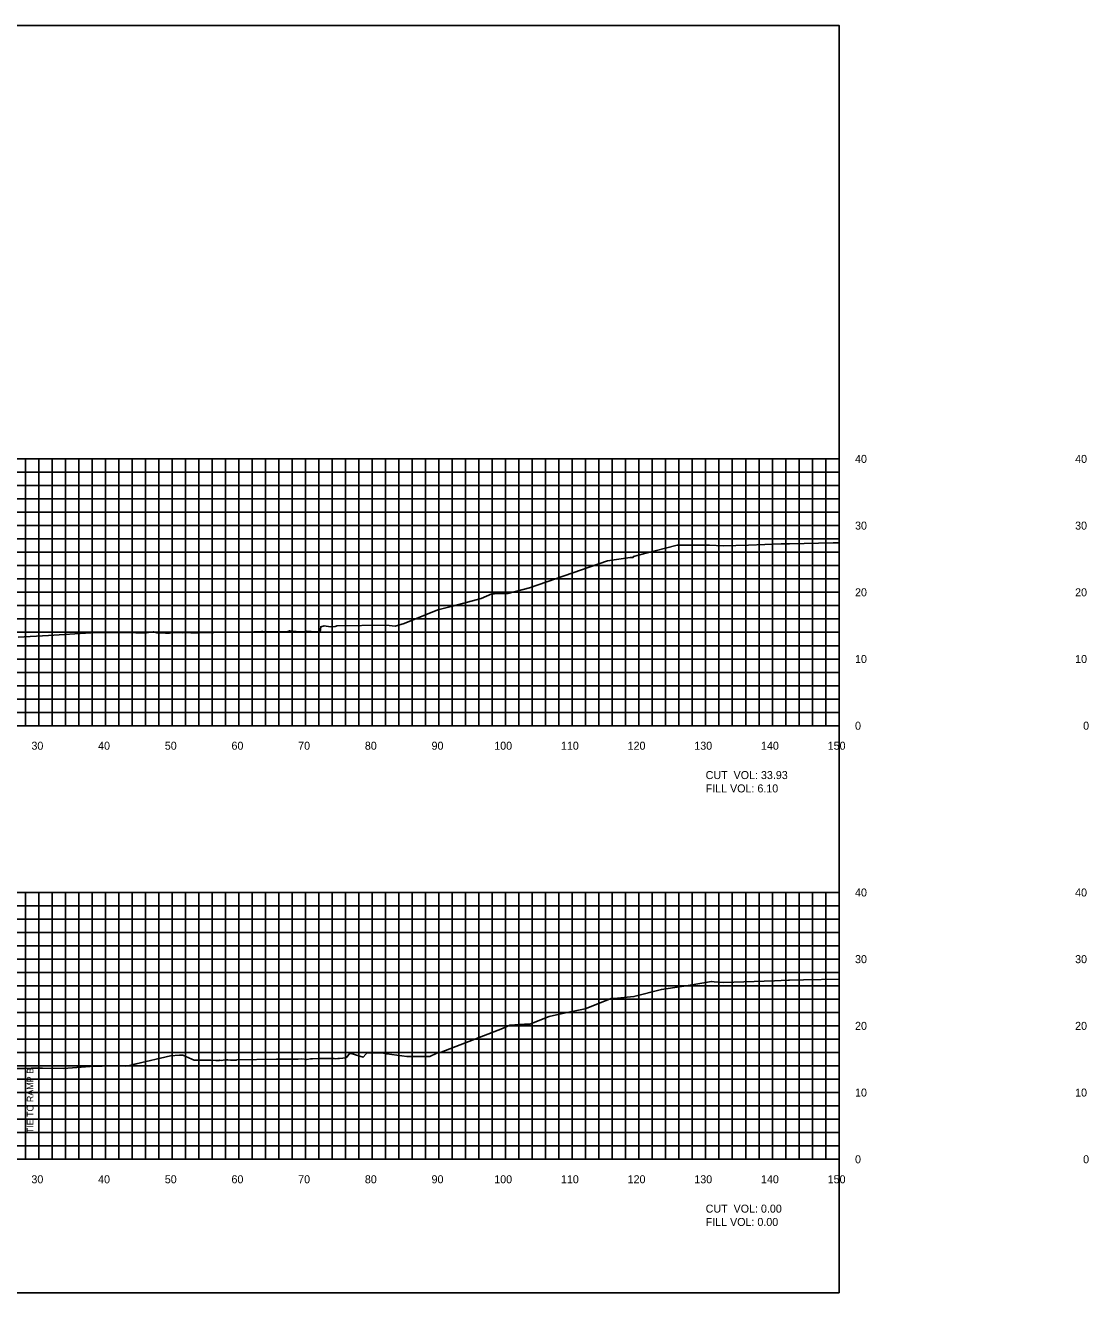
# Model space of a CAD drawing. Extents: x 1797645 to 1803805, y 248417 to 250269.
# Drawn here: x 1802319 to 1802478.4, y 250079.4 to 250269.4 of the extents above; entities that cross this region are included whole.
import ezdxf

# ---------------------------------------------------------------- set-up
doc = ezdxf.new("R2010")
doc.units = 0
for name, color, linetype in [('10', 7, 'Continuous'), ('3', 7, 'Continuous'), ('31', 7, 'Continuous'), ('60', 7, 'Continuous'), ('ANNO-TXT', 7, 'Continuous'), ('Level 62', 7, 'Continuous'), ('M-ROADS', 7, 'Continuous')]:
    doc.layers.add(name, color=color, linetype=linetype)

msp = doc.modelspace()

# ---------------------------------------------------------------- linework, layer by layer
msp.add_lwpolyline([(1802141, 250079.43), (1802441, 250079.43), (1802441, 250269.43), (1802141, 250269.43)], close=True)
at = {"layer": '60'}
for p, q in [((1802441, 250164.43), (1802441, 250204.43)), ((1802441.06, 250204.43), (1802441, 250204.43)), ((1802441.06, 250194.43), (1802441, 250194.43)), ((1802441.06, 250184.43), (1802441, 250184.43)), ((1802441.06, 250174.43), (1802441, 250174.43)), ((1802141, 250164.43), (1802441, 250164.43)), ((1802321, 250164.37), (1802321, 250164.43)), ((1802331, 250164.37), (1802331, 250164.43)), ((1802341, 250164.37), (1802341, 250164.43)), ((1802351, 250164.37), (1802351, 250164.43)), ((1802361, 250164.37), (1802361, 250164.43)), ((1802371, 250164.37), (1802371, 250164.43)), ((1802381, 250164.37), (1802381, 250164.43)), ((1802391, 250164.37), (1802391, 250164.43)), ((1802401, 250164.37), (1802401, 250164.43)), ((1802411, 250164.37), (1802411, 250164.43)), ((1802421, 250164.37), (1802421, 250164.43)), ((1802431, 250164.37), (1802431, 250164.43)), ((1802441, 250164.37), (1802441, 250164.43)), ((1802441.06, 250164.43), (1802441, 250164.43)), ((1802441, 250099.43), (1802441, 250139.43)), ((1802441.06, 250139.43), (1802441, 250139.43)), ((1802441.06, 250129.43), (1802441, 250129.43)), ((1802441.06, 250119.43), (1802441, 250119.43)), ((1802441.06, 250109.43), (1802441, 250109.43)), ((1802141, 250099.43), (1802441, 250099.43)), ((1802321, 250099.37), (1802321, 250099.43)), ((1802331, 250099.37), (1802331, 250099.43)), ((1802341, 250099.37), (1802341, 250099.43)), ((1802351, 250099.37), (1802351, 250099.43)), ((1802361, 250099.37), (1802361, 250099.43)), ((1802371, 250099.37), (1802371, 250099.43)), ((1802381, 250099.37), (1802381, 250099.43)), ((1802391, 250099.37), (1802391, 250099.43)), ((1802401, 250099.37), (1802401, 250099.43)), ((1802411, 250099.37), (1802411, 250099.43)), ((1802421, 250099.37), (1802421, 250099.43)), ((1802431, 250099.37), (1802431, 250099.43)), ((1802441, 250099.37), (1802441, 250099.43)), ((1802441.06, 250099.43), (1802441, 250099.43))]:
    msp.add_line(p, q, dxfattribs=at)
at = {"layer": 'Level 62'}
for p, q in [((1802141, 250204.43), (1802441, 250204.43)), ((1802319, 250164.43), (1802319, 250204.43)), ((1802321, 250164.43), (1802321, 250204.43)), ((1802323, 250164.43), (1802323, 250204.43)), ((1802325, 250164.43), (1802325, 250204.43)), ((1802327, 250164.43), (1802327, 250204.43)), ((1802329, 250164.43), (1802329, 250204.43)), ((1802331, 250164.43), (1802331, 250204.43)), ((1802333, 250164.43), (1802333, 250204.43)), ((1802335, 250164.43), (1802335, 250204.43)), ((1802337, 250164.43), (1802337, 250204.43)), ((1802339, 250164.43), (1802339, 250204.43)), ((1802341, 250164.43), (1802341, 250204.43)), ((1802343, 250164.43), (1802343, 250204.43)), ((1802345, 250164.43), (1802345, 250204.43)), ((1802347, 250164.43), (1802347, 250204.43)), ((1802349, 250164.43), (1802349, 250204.43)), ((1802351, 250164.43), (1802351, 250204.43)), ((1802353, 250164.43), (1802353, 250204.43)), ((1802355, 250164.43), (1802355, 250204.43)), ((1802357, 250164.43), (1802357, 250204.43)), ((1802359, 250164.43), (1802359, 250204.43)), ((1802361, 250164.43), (1802361, 250204.43)), ((1802363, 250164.43), (1802363, 250204.43)), ((1802365, 250164.43), (1802365, 250204.43)), ((1802367, 250164.43), (1802367, 250204.43)), ((1802369, 250164.43), (1802369, 250204.43)), ((1802371, 250164.43), (1802371, 250204.43)), ((1802373, 250164.43), (1802373, 250204.43)), ((1802375, 250164.43), (1802375, 250204.43)), ((1802377, 250164.43), (1802377, 250204.43)), ((1802379, 250164.43), (1802379, 250204.43)), ((1802381, 250164.43), (1802381, 250204.43)), ((1802383, 250164.43), (1802383, 250204.43)), ((1802385, 250164.43), (1802385, 250204.43)), ((1802387, 250164.43), (1802387, 250204.43)), ((1802389, 250164.43), (1802389, 250204.43)), ((1802391, 250164.43), (1802391, 250204.43)), ((1802393, 250164.43), (1802393, 250204.43)), ((1802395, 250164.43), (1802395, 250204.43)), ((1802397, 250164.43), (1802397, 250204.43)), ((1802399, 250164.43), (1802399, 250204.43)), ((1802401, 250164.43), (1802401, 250204.43)), ((1802403, 250164.43), (1802403, 250204.43)), ((1802405, 250164.43), (1802405, 250204.43)), ((1802407, 250164.43), (1802407, 250204.43)), ((1802409, 250164.43), (1802409, 250204.43)), ((1802411, 250164.43), (1802411, 250204.43)), ((1802413, 250164.43), (1802413, 250204.43)), ((1802415, 250164.43), (1802415, 250204.43)), ((1802417, 250164.43), (1802417, 250204.43)), ((1802419, 250164.43), (1802419, 250204.43)), ((1802421, 250164.43), (1802421, 250204.43)), ((1802423, 250164.43), (1802423, 250204.43)), ((1802425, 250164.43), (1802425, 250204.43)), ((1802427, 250164.43), (1802427, 250204.43)), ((1802429, 250164.43), (1802429, 250204.43)), ((1802431, 250164.43), (1802431, 250204.43)), ((1802433, 250164.43), (1802433, 250204.43)), ((1802435, 250164.43), (1802435, 250204.43)), ((1802437, 250164.43), (1802437, 250204.43)), ((1802439, 250164.43), (1802439, 250204.43)), ((1802441, 250164.43), (1802441, 250204.43)), ((1802141, 250202.43), (1802441, 250202.43)), ((1802141, 250200.43), (1802441, 250200.43)), ((1802141, 250198.43), (1802441, 250198.43)), ((1802141, 250196.43), (1802441, 250196.43)), ((1802141, 250194.43), (1802441, 250194.43)), ((1802141, 250192.43), (1802441, 250192.43)), ((1802141, 250190.43), (1802441, 250190.43)), ((1802141, 250188.43), (1802441, 250188.43)), ((1802141, 250186.43), (1802441, 250186.43)), ((1802141, 250184.43), (1802441, 250184.43)), ((1802141, 250182.43), (1802441, 250182.43)), ((1802141, 250180.43), (1802441, 250180.43)), ((1802141, 250178.43), (1802441, 250178.43)), ((1802141, 250176.43), (1802441, 250176.43)), ((1802141, 250174.43), (1802441, 250174.43)), ((1802141, 250172.43), (1802441, 250172.43)), ((1802141, 250170.43), (1802441, 250170.43)), ((1802141, 250168.43), (1802441, 250168.43)), ((1802141, 250166.43), (1802441, 250166.43)), ((1802141, 250164.43), (1802441, 250164.43)), ((1802141, 250139.43), (1802441, 250139.43)), ((1802319, 250099.43), (1802319, 250139.43)), ((1802321, 250099.43), (1802321, 250139.43)), ((1802323, 250099.43), (1802323, 250139.43)), ((1802325, 250099.43), (1802325, 250139.43)), ((1802327, 250099.43), (1802327, 250139.43)), ((1802329, 250099.43), (1802329, 250139.43)), ((1802331, 250099.43), (1802331, 250139.43)), ((1802333, 250099.43), (1802333, 250139.43)), ((1802335, 250099.43), (1802335, 250139.43)), ((1802337, 250099.43), (1802337, 250139.43)), ((1802339, 250099.43), (1802339, 250139.43)), ((1802341, 250099.43), (1802341, 250139.43)), ((1802343, 250099.43), (1802343, 250139.43)), ((1802345, 250099.43), (1802345, 250139.43)), ((1802347, 250099.43), (1802347, 250139.43)), ((1802349, 250099.43), (1802349, 250139.43)), ((1802351, 250099.43), (1802351, 250139.43)), ((1802353, 250099.43), (1802353, 250139.43)), ((1802355, 250099.43), (1802355, 250139.43)), ((1802357, 250099.43), (1802357, 250139.43)), ((1802359, 250099.43), (1802359, 250139.43)), ((1802361, 250099.43), (1802361, 250139.43)), ((1802363, 250099.43), (1802363, 250139.43)), ((1802365, 250099.43), (1802365, 250139.43)), ((1802367, 250099.43), (1802367, 250139.43)), ((1802369, 250099.43), (1802369, 250139.43)), ((1802371, 250099.43), (1802371, 250139.43)), ((1802373, 250099.43), (1802373, 250139.43)), ((1802375, 250099.43), (1802375, 250139.43)), ((1802377, 250099.43), (1802377, 250139.43)), ((1802379, 250099.43), (1802379, 250139.43)), ((1802381, 250099.43), (1802381, 250139.43)), ((1802383, 250099.43), (1802383, 250139.43)), ((1802385, 250099.43), (1802385, 250139.43)), ((1802387, 250099.43), (1802387, 250139.43)), ((1802389, 250099.43), (1802389, 250139.43)), ((1802391, 250099.43), (1802391, 250139.43)), ((1802393, 250099.43), (1802393, 250139.43)), ((1802395, 250099.43), (1802395, 250139.43)), ((1802397, 250099.43), (1802397, 250139.43)), ((1802399, 250099.43), (1802399, 250139.43)), ((1802401, 250099.43), (1802401, 250139.43)), ((1802403, 250099.43), (1802403, 250139.43)), ((1802405, 250099.43), (1802405, 250139.43)), ((1802407, 250099.43), (1802407, 250139.43)), ((1802409, 250099.43), (1802409, 250139.43)), ((1802411, 250099.43), (1802411, 250139.43)), ((1802413, 250099.43), (1802413, 250139.43)), ((1802415, 250099.43), (1802415, 250139.43)), ((1802417, 250099.43), (1802417, 250139.43)), ((1802419, 250099.43), (1802419, 250139.43)), ((1802421, 250099.43), (1802421, 250139.43)), ((1802423, 250099.43), (1802423, 250139.43)), ((1802425, 250099.43), (1802425, 250139.43)), ((1802427, 250099.43), (1802427, 250139.43)), ((1802429, 250099.43), (1802429, 250139.43)), ((1802431, 250099.43), (1802431, 250139.43)), ((1802433, 250099.43), (1802433, 250139.43)), ((1802435, 250099.43), (1802435, 250139.43)), ((1802437, 250099.43), (1802437, 250139.43)), ((1802439, 250099.43), (1802439, 250139.43)), ((1802441, 250099.43), (1802441, 250139.43)), ((1802141, 250137.43), (1802441, 250137.43)), ((1802141, 250135.43), (1802441, 250135.43)), ((1802141, 250133.43), (1802441, 250133.43)), ((1802141, 250131.43), (1802441, 250131.43)), ((1802141, 250129.43), (1802441, 250129.43)), ((1802141, 250127.43), (1802441, 250127.43)), ((1802141, 250125.43), (1802441, 250125.43)), ((1802141, 250123.43), (1802441, 250123.43)), ((1802141, 250121.43), (1802441, 250121.43)), ((1802141, 250119.43), (1802441, 250119.43)), ((1802141, 250117.43), (1802441, 250117.43)), ((1802141, 250115.43), (1802441, 250115.43)), ((1802141, 250113.43), (1802441, 250113.43)), ((1802141, 250111.43), (1802441, 250111.43)), ((1802141, 250109.43), (1802441, 250109.43)), ((1802141, 250107.43), (1802441, 250107.43)), ((1802141, 250105.43), (1802441, 250105.43)), ((1802141, 250103.43), (1802441, 250103.43)), ((1802141, 250101.43), (1802441, 250101.43)), ((1802141, 250099.43), (1802441, 250099.43))]:
    msp.add_line(p, q, dxfattribs=at)
at = {"layer": 'M-ROADS'}
for points in [[(1802317.93, 250177.7), (1802322.45, 250177.96), (1802328.83, 250178.33), (1802333.88, 250178.42), (1802334.22, 250178.4), (1802334.74, 250178.42), (1802335.57, 250178.36), (1802337.13, 250178.33), (1802338.19, 250178.51), (1802338.73, 250178.33), (1802339.26, 250178.34), (1802340, 250178.32), (1802340.59, 250178.29), (1802341.01, 250178.39), (1802341.32, 250178.4), (1802341.87, 250178.38), (1802342.57, 250178.36), (1802343.54, 250178.38), (1802343.8, 250178.37), (1802343.88, 250178.37), (1802344.54, 250178.35), (1802345.02, 250178.35), (1802345.07, 250178.34), (1802349.46, 250178.45), (1802353.26, 250178.51), (1802354.38, 250178.53), (1802354.53, 250178.53), (1802354.69, 250178.52), (1802354.9, 250178.54), (1802355.81, 250178.52), (1802356.14, 250178.52), (1802357.04, 250178.52), (1802357.78, 250178.5), (1802358.25, 250178.49), (1802358.62, 250178.64), (1802358.65, 250178.64), (1802359.61, 250178.54), (1802360.08, 250178.49), (1802360.91, 250178.56), (1802361.13, 250178.61), (1802362.55, 250178.5), (1802362.84, 250178.48), (1802363.2, 250178.48), (1802363.29, 250179.26), (1802363.81, 250179.4), (1802364.76, 250179.24), (1802365.45, 250179.3), (1802365.61, 250179.36), (1802365.72, 250179.41), (1802365.77, 250179.41), (1802373.11, 250179.51), (1802374.46, 250179.37), (1802375.79, 250179.73), (1802380.86, 250181.8), (1802383.26, 250182.42), (1802387.32, 250183.48), (1802388.92, 250184.22), (1802389.34, 250184.22), (1802391.35, 250184.26), (1802394.61, 250185.11), (1802406.3, 250189.17), (1802409.66, 250189.66), (1802409.86, 250189.66), (1802410.11, 250189.66), (1802410.2, 250189.8), (1802411.67, 250190.18), (1802416.74, 250191.5), (1802418.78, 250191.5), (1802420.15, 250191.5), (1802421.16, 250191.5), (1802421.39, 250191.49), (1802421.57, 250191.49), (1802423.64, 250191.39), (1802427.4, 250191.52), (1802432.33, 250191.69), (1802433.03, 250191.71), (1802433.57, 250191.72), (1802440.11, 250191.85), (1802441, 250191.87)], [(1802317.22, 250113.02), (1802319, 250113.05), (1802319.88, 250113.08), (1802320.66, 250113.07), (1802321.58, 250113.07), (1802324.72, 250113.05), (1802329.38, 250113.4), (1802329.59, 250113.41), (1802330.51, 250113.41), (1802331.93, 250113.42), (1802333.68, 250113.43), (1802334, 250113.41), (1802334.45, 250113.42), (1802335.63, 250113.74), (1802340.76, 250114.94), (1802342.08, 250115.05), (1802342.62, 250115.05), (1802343.95, 250114.46), (1802344.3, 250114.3), (1802345.29, 250114.29), (1802345.55, 250114.31), (1802345.71, 250114.29), (1802346.82, 250114.28), (1802347.53, 250114.26), (1802348.07, 250114.25), (1802348.14, 250114.28), (1802348.34, 250114.25), (1802348.93, 250114.34), (1802349.36, 250114.32), (1802349.76, 250114.31), (1802350.63, 250114.3), (1802350.69, 250114.33), (1802356.66, 250114.43), (1802359.18, 250114.45), (1802359.88, 250114.46), (1802360.45, 250114.47), (1802361.22, 250114.41), (1802361.75, 250114.49), (1802362.03, 250114.51), (1802363.01, 250114.53), (1802363.05, 250114.53), (1802363.07, 250114.53), (1802364.39, 250114.56), (1802365.25, 250114.54), (1802365.52, 250114.48), (1802365.83, 250114.52), (1802366.09, 250114.52), (1802367.09, 250114.65), (1802367.49, 250115.15), (1802367.59, 250115.27), (1802367.85, 250115.29), (1802369.64, 250114.73), (1802370.05, 250115.2), (1802370.19, 250115.36), (1802371.51, 250115.37), (1802372.71, 250115.36), (1802373.18, 250115.23), (1802376.17, 250114.86), (1802377.15, 250114.86), (1802378.45, 250114.86), (1802379.66, 250114.83), (1802380.67, 250115.34), (1802381.36, 250115.48), (1802390.54, 250119.03), (1802391.64, 250119.54), (1802393.86, 250119.66), (1802394.65, 250119.7), (1802397.51, 250120.82), (1802399.98, 250121.36), (1802402.92, 250122), (1802406.83, 250123.51), (1802407.78, 250123.6), (1802410.25, 250123.82), (1802414.36, 250124.89), (1802418.4, 250125.49), (1802421.86, 250126.09), (1802422.29, 250126.04), (1802423.66, 250125.91), (1802431.34, 250126.2), (1802432.34, 250126.24), (1802433.44, 250126.27), (1802433.58, 250126.27), (1802435.68, 250126.31), (1802441, 250126.42)]]:
    msp.add_lwpolyline(points, dxfattribs=at)

# ---------------------------------------------------------------- texts
at = {"layer": '10'}
for s, p in [('30', (1802319.9, 250160.83)), ('40', (1802329.9, 250160.83)), ('50', (1802339.9, 250160.83)), ('60', (1802349.9, 250160.83)), ('70', (1802359.9, 250160.83)), ('80', (1802369.9, 250160.83)), ('90', (1802379.9, 250160.83)), ('100', (1802389.3, 250160.83)), ('110', (1802399.3, 250160.83)), ('120', (1802409.3, 250160.83)), ('130', (1802419.3, 250160.83)), ('140', (1802429.3, 250160.83)), ('150', (1802439.3, 250160.83)), ('30', (1802319.9, 250095.83)), ('40', (1802329.9, 250095.83)), ('50', (1802339.9, 250095.83)), ('60', (1802349.9, 250095.83)), ('70', (1802359.9, 250095.83)), ('80', (1802369.9, 250095.83)), ('90', (1802379.9, 250095.83)), ('100', (1802389.3, 250095.83)), ('110', (1802399.3, 250095.83)), ('120', (1802409.3, 250095.83)), ('130', (1802419.3, 250095.83)), ('140', (1802429.3, 250095.83)), ('150', (1802439.3, 250095.83))]:
    msp.add_text(s, height=1.2, dxfattribs=at).set_placement(p)
at = {"layer": '3'}
msp.add_text('TIE TO RAMP B', height=1, rotation=90, dxfattribs=at).set_placement((1802320.21, 250103.32))
at = {"layer": '31'}
for s, p in [('40', (1802443.4, 250203.83)), ('40', (1802476.4, 250203.83)), ('30', (1802443.4, 250193.83)), ('30', (1802476.4, 250193.83)), ('20', (1802443.4, 250183.83)), ('20', (1802476.4, 250183.83)), ('10', (1802443.4, 250173.83)), ('10', (1802476.4, 250173.83)), ('0', (1802443.4, 250163.83)), ('0', (1802477.6, 250163.83)), ('40', (1802443.4, 250138.83)), ('40', (1802476.4, 250138.83)), ('30', (1802443.4, 250128.83)), ('30', (1802476.4, 250128.83)), ('20', (1802443.4, 250118.83)), ('20', (1802476.4, 250118.83)), ('10', (1802443.4, 250108.83)), ('10', (1802476.4, 250108.83)), ('0', (1802443.4, 250098.83)), ('0', (1802477.6, 250098.83))]:
    msp.add_text(s, height=1.2, dxfattribs=at).set_placement(p)
at = {"layer": 'ANNO-TXT'}
for s, p in [('CUT  VOL: 33.93', (1802421, 250156.43)), ('FILL VOL: 6.10', (1802421, 250154.43)), ('CUT  VOL: 0.00', (1802421, 250091.43)), ('FILL VOL: 0.00', (1802421, 250089.43))]:
    msp.add_text(s, height=1.2, dxfattribs=at).set_placement(p)

doc.saveas('drawing.dxf')
